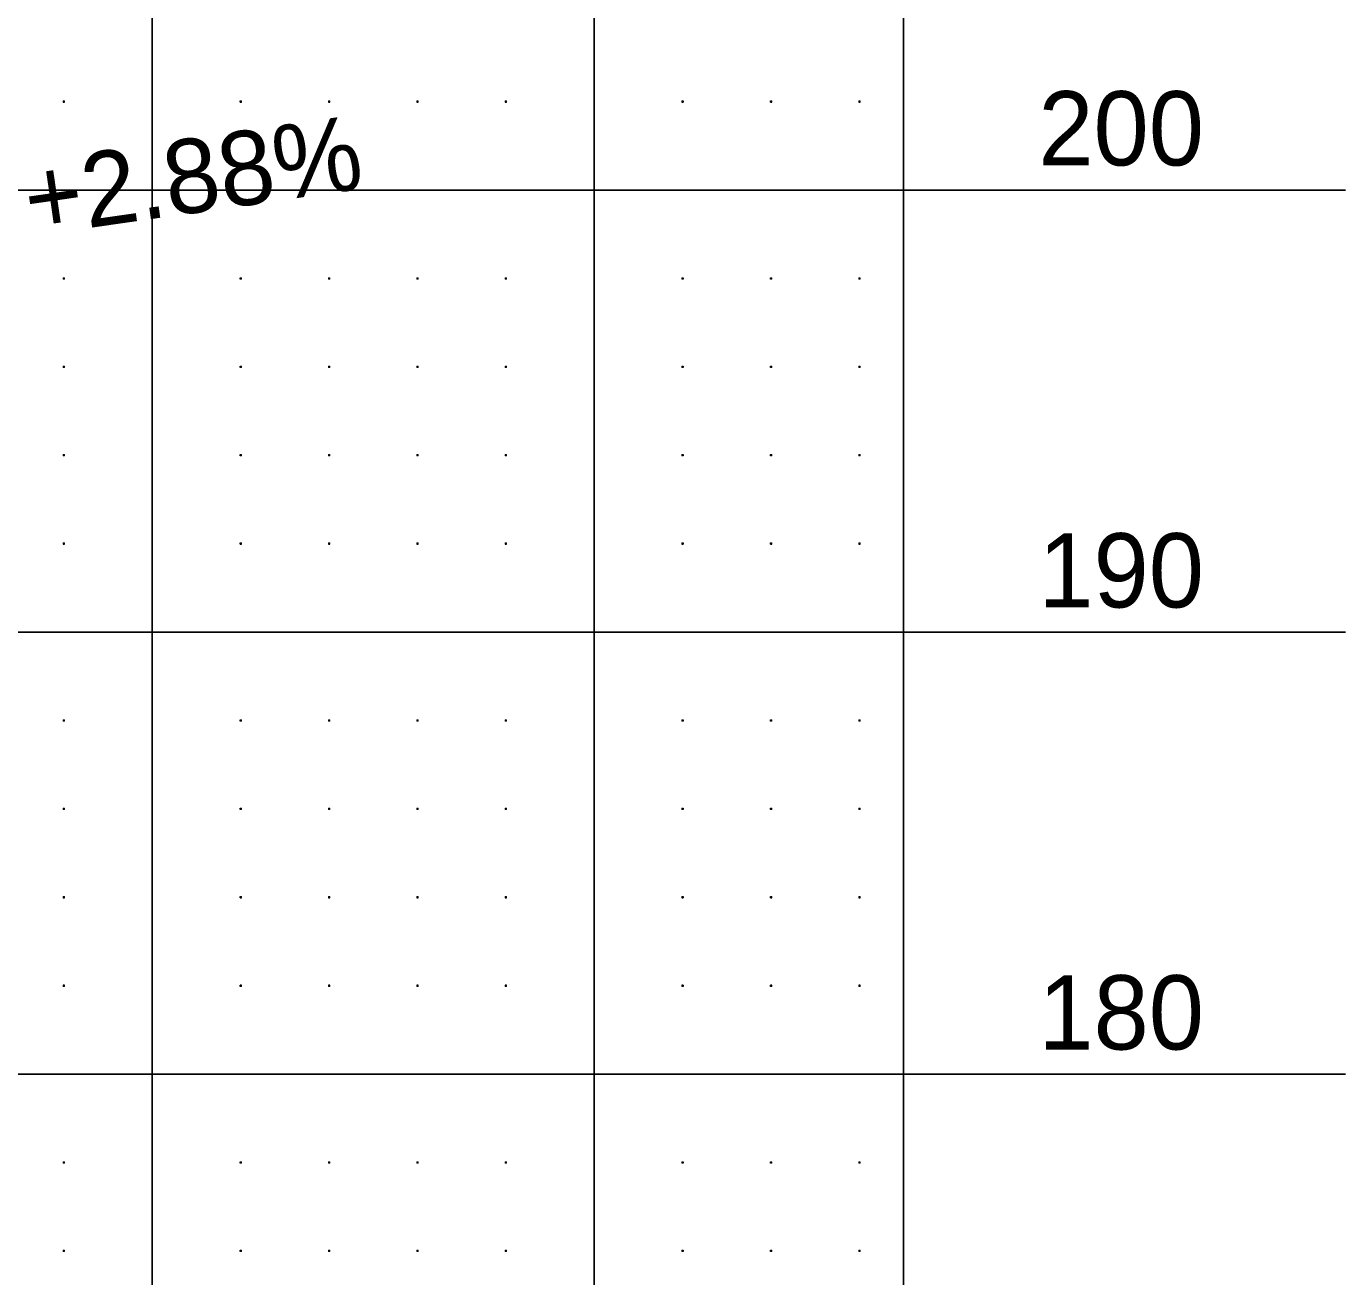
# Model space of a CAD drawing. Extents: x 471 to 2121, y 140 to 650.
# Drawn here: x 1971.8 to 2121.1, y 277.1 to 418.5 of the extents above; entities that cross this region are included whole.
import ezdxf

# ---------------------------------------------------------------- set-up
doc = ezdxf.new("R2010")
doc.units = 0
for name, color, linetype in [('DSN_DRFT_Border Grid', 7, 'Continuous'), ('DSN_RDWY_Prof Annotation', 7, 'Continuous'), ('Triangles', 7, 'Continuous')]:
    doc.layers.add(name, color=color, linetype=linetype)

msp = doc.modelspace()

# ---------------------------------------------------------------- linework, layer by layer
at = {"layer": 'DSN_DRFT_Border Grid'}
for p, q in [((1986.06, 150), (1986.06, 650)), ((1986.06, 150), (1986.06, 650)), ((2036.06, 150), (2036.06, 650)), ((2036.06, 150), (2036.06, 650)), ((2071.06, 150), (2071.06, 650)), ((2071.06, 150), (2071.06, 650)), ((1976.18, 410), (1975.94, 410)), ((1976.18, 410), (1975.94, 410)), ((1976.06, 410.12), (1976.06, 409.88)), ((1976.06, 410.12), (1976.06, 409.88)), ((1996.18, 410), (1995.94, 410)), ((1996.18, 410), (1995.94, 410)), ((1996.06, 410.12), (1996.06, 409.88)), ((1996.06, 410.12), (1996.06, 409.88)), ((2006.18, 410), (2005.94, 410)), ((2006.18, 410), (2005.94, 410)), ((2006.06, 410.12), (2006.06, 409.88)), ((2006.06, 410.12), (2006.06, 409.88)), ((2016.18, 410), (2015.94, 410)), ((2016.18, 410), (2015.94, 410)), ((2016.06, 410.12), (2016.06, 409.88)), ((2016.06, 410.12), (2016.06, 409.88)), ((2026.18, 410), (2025.94, 410)), ((2026.18, 410), (2025.94, 410)), ((2026.06, 410.12), (2026.06, 409.88)), ((2026.06, 410.12), (2026.06, 409.88)), ((2046.18, 410), (2045.94, 410)), ((2046.18, 410), (2045.94, 410)), ((2046.06, 410.12), (2046.06, 409.88)), ((2046.06, 410.12), (2046.06, 409.88)), ((2056.18, 410), (2055.94, 410)), ((2056.18, 410), (2055.94, 410)), ((2056.06, 410.12), (2056.06, 409.88)), ((2056.06, 410.12), (2056.06, 409.88)), ((2066.18, 410), (2065.94, 410)), ((2066.18, 410), (2065.94, 410)), ((2066.06, 410.12), (2066.06, 409.88)), ((2066.06, 410.12), (2066.06, 409.88)), ((521.06, 400), (2071.06, 400)), ((521.06, 400), (2071.06, 400)), ((2071.06, 400), (2121.06, 400)), ((1976.18, 390), (1975.94, 390)), ((1976.18, 390), (1975.94, 390)), ((1976.06, 390.12), (1976.06, 389.88)), ((1976.06, 390.12), (1976.06, 389.88)), ((1996.18, 390), (1995.94, 390)), ((1996.18, 390), (1995.94, 390)), ((1996.06, 390.12), (1996.06, 389.88)), ((1996.06, 390.12), (1996.06, 389.88)), ((2006.18, 390), (2005.94, 390)), ((2006.18, 390), (2005.94, 390)), ((2006.06, 390.12), (2006.06, 389.88)), ((2006.06, 390.12), (2006.06, 389.88)), ((2016.18, 390), (2015.94, 390)), ((2016.18, 390), (2015.94, 390)), ((2016.06, 390.12), (2016.06, 389.88)), ((2016.06, 390.12), (2016.06, 389.88)), ((2026.18, 390), (2025.94, 390)), ((2026.18, 390), (2025.94, 390)), ((2026.06, 390.12), (2026.06, 389.88)), ((2026.06, 390.12), (2026.06, 389.88)), ((2046.18, 390), (2045.94, 390)), ((2046.18, 390), (2045.94, 390)), ((2046.06, 390.12), (2046.06, 389.88)), ((2046.06, 390.12), (2046.06, 389.88)), ((2056.18, 390), (2055.94, 390)), ((2056.18, 390), (2055.94, 390)), ((2056.06, 390.12), (2056.06, 389.88)), ((2056.06, 390.12), (2056.06, 389.88)), ((2066.18, 390), (2065.94, 390)), ((2066.18, 390), (2065.94, 390)), ((2066.06, 390.12), (2066.06, 389.88)), ((2066.06, 390.12), (2066.06, 389.88)), ((1976.18, 380), (1975.94, 380)), ((1976.18, 380), (1975.94, 380)), ((1976.06, 380.12), (1976.06, 379.88)), ((1976.06, 380.12), (1976.06, 379.88)), ((1996.18, 380), (1995.94, 380)), ((1996.18, 380), (1995.94, 380)), ((1996.06, 380.12), (1996.06, 379.88)), ((1996.06, 380.12), (1996.06, 379.88)), ((2006.18, 380), (2005.94, 380)), ((2006.18, 380), (2005.94, 380)), ((2006.06, 380.12), (2006.06, 379.88)), ((2006.06, 380.12), (2006.06, 379.88)), ((2016.18, 380), (2015.94, 380)), ((2016.18, 380), (2015.94, 380)), ((2016.06, 380.12), (2016.06, 379.88)), ((2016.06, 380.12), (2016.06, 379.88)), ((2026.18, 380), (2025.94, 380)), ((2026.18, 380), (2025.94, 380)), ((2026.06, 380.12), (2026.06, 379.88)), ((2026.06, 380.12), (2026.06, 379.88)), ((2046.18, 380), (2045.94, 380)), ((2046.18, 380), (2045.94, 380)), ((2046.06, 380.12), (2046.06, 379.88)), ((2046.06, 380.12), (2046.06, 379.88)), ((2056.18, 380), (2055.94, 380)), ((2056.18, 380), (2055.94, 380)), ((2056.06, 380.12), (2056.06, 379.88)), ((2056.06, 380.12), (2056.06, 379.88)), ((2066.18, 380), (2065.94, 380)), ((2066.18, 380), (2065.94, 380)), ((2066.06, 380.12), (2066.06, 379.88)), ((2066.06, 380.12), (2066.06, 379.88)), ((1976.18, 370), (1975.94, 370)), ((1976.18, 370), (1975.94, 370)), ((1976.06, 370.12), (1976.06, 369.88)), ((1976.06, 370.12), (1976.06, 369.88)), ((1996.18, 370), (1995.94, 370)), ((1996.18, 370), (1995.94, 370)), ((1996.06, 370.12), (1996.06, 369.88)), ((1996.06, 370.12), (1996.06, 369.88)), ((2006.18, 370), (2005.94, 370)), ((2006.18, 370), (2005.94, 370)), ((2006.06, 370.12), (2006.06, 369.88)), ((2006.06, 370.12), (2006.06, 369.88)), ((2016.18, 370), (2015.94, 370)), ((2016.18, 370), (2015.94, 370)), ((2016.06, 370.12), (2016.06, 369.88)), ((2016.06, 370.12), (2016.06, 369.88)), ((2026.18, 370), (2025.94, 370)), ((2026.18, 370), (2025.94, 370)), ((2026.06, 370.12), (2026.06, 369.88)), ((2026.06, 370.12), (2026.06, 369.88)), ((2046.18, 370), (2045.94, 370)), ((2046.18, 370), (2045.94, 370)), ((2046.06, 370.12), (2046.06, 369.88)), ((2046.06, 370.12), (2046.06, 369.88)), ((2056.18, 370), (2055.94, 370)), ((2056.18, 370), (2055.94, 370)), ((2056.06, 370.12), (2056.06, 369.88)), ((2056.06, 370.12), (2056.06, 369.88)), ((2066.18, 370), (2065.94, 370)), ((2066.18, 370), (2065.94, 370)), ((2066.06, 370.12), (2066.06, 369.88)), ((2066.06, 370.12), (2066.06, 369.88)), ((1976.18, 360), (1975.94, 360)), ((1976.18, 360), (1975.94, 360)), ((1976.06, 360.12), (1976.06, 359.88)), ((1976.06, 360.12), (1976.06, 359.88)), ((1996.18, 360), (1995.94, 360)), ((1996.18, 360), (1995.94, 360)), ((1996.06, 360.12), (1996.06, 359.88)), ((1996.06, 360.12), (1996.06, 359.88)), ((2006.18, 360), (2005.94, 360)), ((2006.18, 360), (2005.94, 360)), ((2006.06, 360.12), (2006.06, 359.88)), ((2006.06, 360.12), (2006.06, 359.88)), ((2016.18, 360), (2015.94, 360)), ((2016.18, 360), (2015.94, 360)), ((2016.06, 360.12), (2016.06, 359.88)), ((2016.06, 360.12), (2016.06, 359.88)), ((2026.18, 360), (2025.94, 360)), ((2026.18, 360), (2025.94, 360)), ((2026.06, 360.12), (2026.06, 359.88)), ((2026.06, 360.12), (2026.06, 359.88)), ((2046.18, 360), (2045.94, 360)), ((2046.18, 360), (2045.94, 360)), ((2046.06, 360.12), (2046.06, 359.88)), ((2046.06, 360.12), (2046.06, 359.88)), ((2056.18, 360), (2055.94, 360)), ((2056.18, 360), (2055.94, 360)), ((2056.06, 360.12), (2056.06, 359.88)), ((2056.06, 360.12), (2056.06, 359.88)), ((2066.18, 360), (2065.94, 360)), ((2066.18, 360), (2065.94, 360)), ((2066.06, 360.12), (2066.06, 359.88)), ((2066.06, 360.12), (2066.06, 359.88)), ((521.06, 350), (2071.06, 350)), ((521.06, 350), (2071.06, 350)), ((2071.06, 350), (2121.06, 350)), ((1976.18, 340), (1975.94, 340)), ((1976.18, 340), (1975.94, 340)), ((1976.06, 340.12), (1976.06, 339.88)), ((1976.06, 340.12), (1976.06, 339.88)), ((1996.18, 340), (1995.94, 340)), ((1996.18, 340), (1995.94, 340)), ((1996.06, 340.12), (1996.06, 339.88)), ((1996.06, 340.12), (1996.06, 339.88)), ((2006.18, 340), (2005.94, 340)), ((2006.18, 340), (2005.94, 340)), ((2006.06, 340.12), (2006.06, 339.88)), ((2006.06, 340.12), (2006.06, 339.88)), ((2016.18, 340), (2015.94, 340)), ((2016.18, 340), (2015.94, 340)), ((2016.06, 340.12), (2016.06, 339.88)), ((2016.06, 340.12), (2016.06, 339.88)), ((2026.18, 340), (2025.94, 340)), ((2026.18, 340), (2025.94, 340)), ((2026.06, 340.12), (2026.06, 339.88)), ((2026.06, 340.12), (2026.06, 339.88)), ((2046.18, 340), (2045.94, 340)), ((2046.18, 340), (2045.94, 340)), ((2046.06, 340.12), (2046.06, 339.88)), ((2046.06, 340.12), (2046.06, 339.88)), ((2056.18, 340), (2055.94, 340)), ((2056.18, 340), (2055.94, 340)), ((2056.06, 340.12), (2056.06, 339.88)), ((2056.06, 340.12), (2056.06, 339.88)), ((2066.18, 340), (2065.94, 340)), ((2066.18, 340), (2065.94, 340)), ((2066.06, 340.12), (2066.06, 339.88)), ((2066.06, 340.12), (2066.06, 339.88)), ((1976.18, 330), (1975.94, 330)), ((1976.18, 330), (1975.94, 330)), ((1976.06, 330.12), (1976.06, 329.88)), ((1976.06, 330.12), (1976.06, 329.88)), ((1996.18, 330), (1995.94, 330)), ((1996.18, 330), (1995.94, 330)), ((1996.06, 330.12), (1996.06, 329.88)), ((1996.06, 330.12), (1996.06, 329.88)), ((2006.18, 330), (2005.94, 330)), ((2006.18, 330), (2005.94, 330)), ((2006.06, 330.12), (2006.06, 329.88)), ((2006.06, 330.12), (2006.06, 329.88)), ((2016.18, 330), (2015.94, 330)), ((2016.18, 330), (2015.94, 330)), ((2016.06, 330.12), (2016.06, 329.88)), ((2016.06, 330.12), (2016.06, 329.88)), ((2026.18, 330), (2025.94, 330)), ((2026.18, 330), (2025.94, 330)), ((2026.06, 330.12), (2026.06, 329.88)), ((2026.06, 330.12), (2026.06, 329.88)), ((2046.18, 330), (2045.94, 330)), ((2046.18, 330), (2045.94, 330)), ((2046.06, 330.12), (2046.06, 329.88)), ((2046.06, 330.12), (2046.06, 329.88)), ((2056.18, 330), (2055.94, 330)), ((2056.18, 330), (2055.94, 330)), ((2056.06, 330.12), (2056.06, 329.88)), ((2056.06, 330.12), (2056.06, 329.88)), ((2066.18, 330), (2065.94, 330)), ((2066.18, 330), (2065.94, 330)), ((2066.06, 330.12), (2066.06, 329.88)), ((2066.06, 330.12), (2066.06, 329.88)), ((1976.18, 320), (1975.94, 320)), ((1976.18, 320), (1975.94, 320)), ((1976.06, 320.12), (1976.06, 319.88)), ((1976.06, 320.12), (1976.06, 319.88)), ((1996.18, 320), (1995.94, 320)), ((1996.18, 320), (1995.94, 320)), ((1996.06, 320.12), (1996.06, 319.88)), ((1996.06, 320.12), (1996.06, 319.88)), ((2006.18, 320), (2005.94, 320)), ((2006.18, 320), (2005.94, 320)), ((2006.06, 320.12), (2006.06, 319.88)), ((2006.06, 320.12), (2006.06, 319.88)), ((2016.18, 320), (2015.94, 320)), ((2016.18, 320), (2015.94, 320)), ((2016.06, 320.12), (2016.06, 319.88)), ((2016.06, 320.12), (2016.06, 319.88)), ((2026.18, 320), (2025.94, 320)), ((2026.18, 320), (2025.94, 320)), ((2026.06, 320.12), (2026.06, 319.88)), ((2026.06, 320.12), (2026.06, 319.88)), ((2046.18, 320), (2045.94, 320)), ((2046.18, 320), (2045.94, 320)), ((2046.06, 320.12), (2046.06, 319.88)), ((2046.06, 320.12), (2046.06, 319.88)), ((2056.18, 320), (2055.94, 320)), ((2056.18, 320), (2055.94, 320)), ((2056.06, 320.12), (2056.06, 319.88)), ((2056.06, 320.12), (2056.06, 319.88)), ((2066.18, 320), (2065.94, 320)), ((2066.18, 320), (2065.94, 320)), ((2066.06, 320.12), (2066.06, 319.88)), ((2066.06, 320.12), (2066.06, 319.88)), ((1976.18, 310), (1975.94, 310)), ((1976.18, 310), (1975.94, 310)), ((1976.06, 310.12), (1976.06, 309.88)), ((1976.06, 310.12), (1976.06, 309.88)), ((1996.18, 310), (1995.94, 310)), ((1996.18, 310), (1995.94, 310)), ((1996.06, 310.12), (1996.06, 309.88)), ((1996.06, 310.12), (1996.06, 309.88)), ((2006.18, 310), (2005.94, 310)), ((2006.18, 310), (2005.94, 310)), ((2006.06, 310.12), (2006.06, 309.88)), ((2006.06, 310.12), (2006.06, 309.88)), ((2016.18, 310), (2015.94, 310)), ((2016.18, 310), (2015.94, 310)), ((2016.06, 310.12), (2016.06, 309.88)), ((2016.06, 310.12), (2016.06, 309.88)), ((2026.18, 310), (2025.94, 310)), ((2026.18, 310), (2025.94, 310)), ((2026.06, 310.12), (2026.06, 309.88)), ((2026.06, 310.12), (2026.06, 309.88)), ((2046.18, 310), (2045.94, 310)), ((2046.18, 310), (2045.94, 310)), ((2046.06, 310.12), (2046.06, 309.88)), ((2046.06, 310.12), (2046.06, 309.88)), ((2056.18, 310), (2055.94, 310)), ((2056.18, 310), (2055.94, 310)), ((2056.06, 310.12), (2056.06, 309.88)), ((2056.06, 310.12), (2056.06, 309.88)), ((2066.18, 310), (2065.94, 310)), ((2066.18, 310), (2065.94, 310)), ((2066.06, 310.12), (2066.06, 309.88)), ((2066.06, 310.12), (2066.06, 309.88)), ((521.06, 300), (2071.06, 300)), ((521.06, 300), (2071.06, 300)), ((2071.06, 300), (2121.06, 300)), ((1976.18, 290), (1975.94, 290)), ((1976.18, 290), (1975.94, 290)), ((1976.06, 290.12), (1976.06, 289.88)), ((1976.06, 290.12), (1976.06, 289.88)), ((1996.18, 290), (1995.94, 290)), ((1996.18, 290), (1995.94, 290)), ((1996.06, 290.12), (1996.06, 289.88)), ((1996.06, 290.12), (1996.06, 289.88)), ((2006.18, 290), (2005.94, 290)), ((2006.18, 290), (2005.94, 290)), ((2006.06, 290.12), (2006.06, 289.88)), ((2006.06, 290.12), (2006.06, 289.88)), ((2016.18, 290), (2015.94, 290)), ((2016.18, 290), (2015.94, 290)), ((2016.06, 290.12), (2016.06, 289.88)), ((2016.06, 290.12), (2016.06, 289.88)), ((2026.18, 290), (2025.94, 290)), ((2026.18, 290), (2025.94, 290)), ((2026.06, 290.12), (2026.06, 289.88)), ((2026.06, 290.12), (2026.06, 289.88)), ((2046.18, 290), (2045.94, 290)), ((2046.18, 290), (2045.94, 290)), ((2046.06, 290.12), (2046.06, 289.88)), ((2046.06, 290.12), (2046.06, 289.88)), ((2056.18, 290), (2055.94, 290)), ((2056.18, 290), (2055.94, 290)), ((2056.06, 290.12), (2056.06, 289.88)), ((2056.06, 290.12), (2056.06, 289.88)), ((2066.18, 290), (2065.94, 290)), ((2066.18, 290), (2065.94, 290)), ((2066.06, 290.12), (2066.06, 289.88)), ((2066.06, 290.12), (2066.06, 289.88)), ((1976.18, 280), (1975.94, 280)), ((1976.18, 280), (1975.94, 280)), ((1976.06, 280.12), (1976.06, 279.88)), ((1976.06, 280.12), (1976.06, 279.88)), ((1996.18, 280), (1995.94, 280)), ((1996.18, 280), (1995.94, 280)), ((1996.06, 280.12), (1996.06, 279.88)), ((1996.06, 280.12), (1996.06, 279.88)), ((2006.18, 280), (2005.94, 280)), ((2006.18, 280), (2005.94, 280)), ((2006.06, 280.12), (2006.06, 279.88)), ((2006.06, 280.12), (2006.06, 279.88)), ((2016.18, 280), (2015.94, 280)), ((2016.18, 280), (2015.94, 280)), ((2016.06, 280.12), (2016.06, 279.88)), ((2016.06, 280.12), (2016.06, 279.88)), ((2026.18, 280), (2025.94, 280)), ((2026.18, 280), (2025.94, 280)), ((2026.06, 280.12), (2026.06, 279.88)), ((2026.06, 280.12), (2026.06, 279.88)), ((2046.18, 280), (2045.94, 280)), ((2046.18, 280), (2045.94, 280)), ((2046.06, 280.12), (2046.06, 279.88)), ((2046.06, 280.12), (2046.06, 279.88)), ((2056.18, 280), (2055.94, 280)), ((2056.18, 280), (2055.94, 280)), ((2056.06, 280.12), (2056.06, 279.88)), ((2056.06, 280.12), (2056.06, 279.88)), ((2066.18, 280), (2065.94, 280)), ((2066.18, 280), (2065.94, 280)), ((2066.06, 280.12), (2066.06, 279.88)), ((2066.06, 280.12), (2066.06, 279.88))]:
    msp.add_line(p, q, dxfattribs=at)

# ---------------------------------------------------------------- texts
at = {"layer": 'DSN_RDWY_Prof Annotation'}
for s, p in [('200', (2086.3, 402.78)), ('200', (2086.3, 402.78)), ('190', (2086.3, 352.78)), ('190', (2086.3, 352.78)), ('180', (2086.3, 302.78)), ('180', (2086.3, 302.78))]:
    msp.add_text(s, height=8.4, dxfattribs=at).set_placement(p)
at = {"layer": 'Triangles'}
msp.add_text('+2.88%', height=8.4, rotation=8.1849, dxfattribs=at).set_placement((1972.21, 394.74))

doc.saveas('drawing.dxf')
